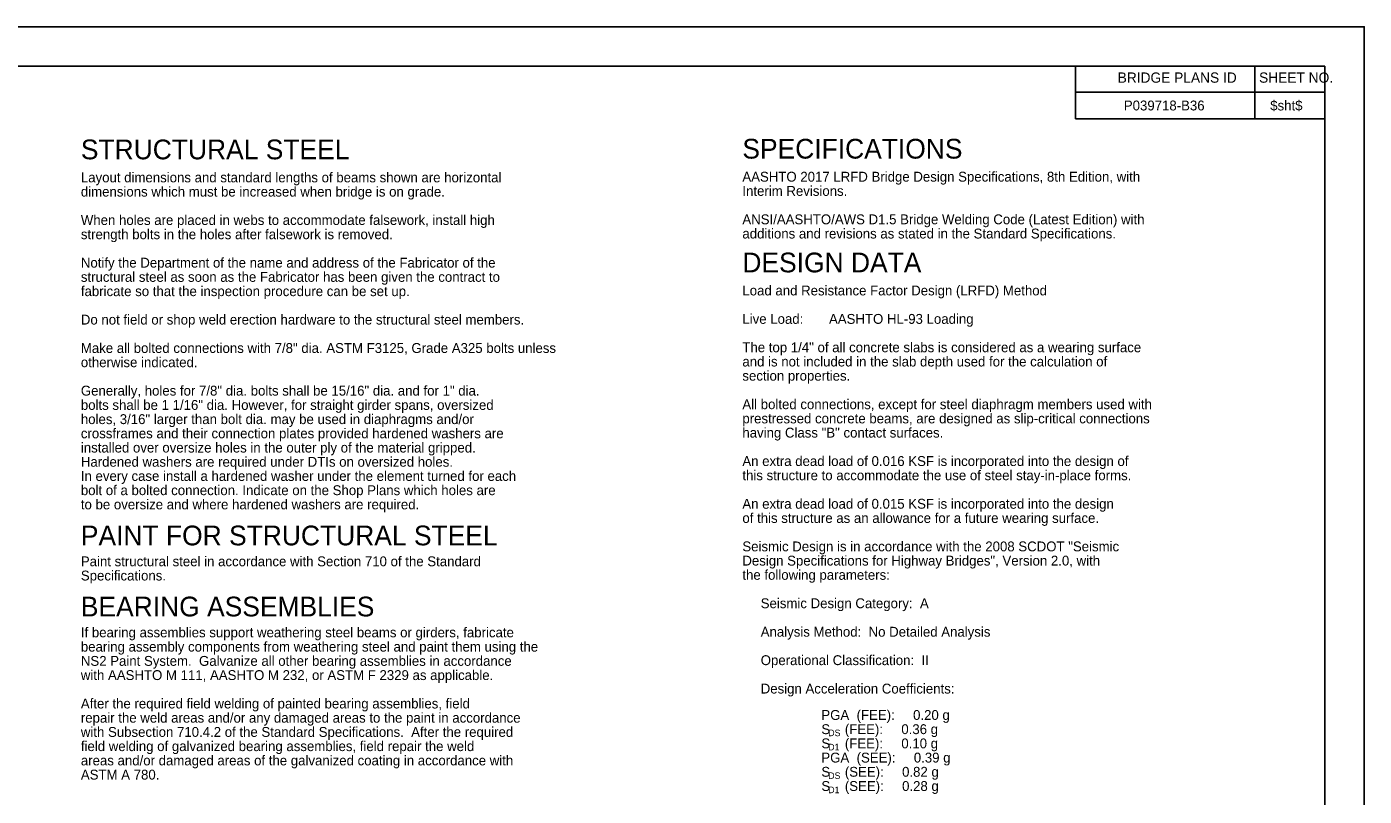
# Model space of a CAD drawing. Extents: x -1.3 to 34.8, y 0.8 to 22.8.
# Drawn here: x 17.75 to 34.68, y 13.07 to 22.82 of the extents above; entities that cross this region are included whole.
import ezdxf

# ---------------------------------------------------------------- set-up
doc = ezdxf.new("R2010")
doc.units = 0
for name, color, linetype in [('BR_BORDER LINES', 7, 'Continuous'), ('BR_TEXT', 7, 'Continuous'), ('Level 31', 7, 'Continuous')]:
    doc.layers.add(name, color=color, linetype=linetype)

msp = doc.modelspace()

# ---------------------------------------------------------------- linework, layer by layer
at = {"layer": 'BR_BORDER LINES'}
for p, q in [((34.177, 22.318), (0.511, 22.318)), ((31.024, 21.651), (31.024, 22.318)), ((33.291, 21.651), (33.291, 22.318)), ((34.177, 1.318), (34.177, 22.318)), ((31.024, 21.989), (34.177, 21.989)), ((33.291, 21.989), (34.177, 21.989)), ((34.177, 21.651), (31.024, 21.651))]:
    msp.add_line(p, q, dxfattribs=at)
at = {"layer": 'Level 31'}
msp.add_lwpolyline([(-1.323, 0.818), (34.677, 0.818), (34.677, 22.818), (-1.323, 22.818)], close=True, dxfattribs=at)

# ---------------------------------------------------------------- texts
at = {"layer": 'BR_TEXT'}
for s, height, p in [('BRIDGE PLANS ID', 0.13, (31.556, 22.109)), ('SHEET NO.', 0.13, (33.346, 22.109)), ('P039718-B36', 0.125, (31.634, 21.758)), ('$sht$', 0.125, (33.487, 21.758)), ('STRUCTURAL STEEL', 0.25, (18.431, 21.139)), ('SPECIFICATIONS', 0.25, (26.805, 21.148)), ('Layout dimensions and standard lengths of beams shown are horizontal ', 0.125, (18.431, 20.847)), ('AASHTO 2017 LRFD Bridge Design Specifications, 8th Edition, with', 0.125, (26.805, 20.856)), ('dimensions which must be increased when bridge is on grade.', 0.125, (18.431, 20.667)), ('Interim Revisions. ', 0.125, (26.805, 20.676)), ('When holes are placed in webs to accommodate falsework, install high', 0.125, (18.431, 20.307)), ('ANSI/AASHTO/AWS D1.5 Bridge Welding Code (Latest Edition) with', 0.125, (26.805, 20.316)), ('strength bolts in the holes after falsework is removed.', 0.125, (18.431, 20.127)), ('additions and revisions as stated in the Standard Specifications.', 0.125, (26.805, 20.136)), ('Notify the Department of the name and address of the Fabricator of the ', 0.125, (18.431, 19.767)), ('DESIGN DATA', 0.25, (26.805, 19.707)), ('structural steel as soon as the Fabricator has been given the contract to ', 0.125, (18.431, 19.587)), ('fabricate so that the inspection procedure can be set up.', 0.125, (18.431, 19.406)), ('Load and Resistance Factor Design (LRFD) Method', 0.125, (26.805, 19.415)), ('Do not field or shop weld erection hardware to the structural steel members. ', 0.125, (18.431, 19.046)), ('Live Load:       AASHTO HL-93 Loading ', 0.125, (26.805, 19.055)), ('Make all bolted connections with 7/8" dia. ASTM F3125, Grade A325 bolts unless', 0.125, (18.431, 18.686)), ('The top 1/4" of all concrete slabs is considered as a wearing surface ', 0.125, (26.805, 18.695)), ('otherwise indicated.', 0.125, (18.431, 18.506)), ('and is not included in the slab depth used for the calculation of ', 0.125, (26.805, 18.515)), ('section properties.', 0.125, (26.805, 18.335)), ('Generally, holes for 7/8" dia. bolts shall be 15/16" dia. and for 1" dia.', 0.125, (18.431, 18.146)), ('bolts shall be 1 1/16" dia. However, for straight girder spans, oversized', 0.125, (18.431, 17.965)), ('All bolted connections, except for steel diaphragm members used with', 0.125, (26.805, 17.974)), ('holes, 3/16" larger than bolt dia. may be used in diaphragms and/or', 0.125, (18.431, 17.785)), ('prestressed concrete beams, are designed as slip-critical connections', 0.125, (26.805, 17.794)), ('crossframes and their connection plates provided hardened washers are', 0.125, (18.431, 17.605)), ('having Class "B" contact surfaces.', 0.125, (26.805, 17.614)), ('installed over oversize holes in the outer ply of the material gripped. ', 0.125, (18.431, 17.425)), ('Hardened washers are required under DTIs on oversized holes.', 0.125, (18.431, 17.245)), ('An extra dead load of 0.016 KSF is incorporated into the design of ', 0.125, (26.805, 17.254)), ('In every case install a hardened washer under the element turned for each', 0.125, (18.431, 17.065)), ('this structure to accommodate the use of steel stay-in-place forms.', 0.125, (26.805, 17.074)), ('bolt of a bolted connection. Indicate on the Shop Plans which holes are', 0.125, (18.431, 16.885)), ('to be oversize and where hardened washers are required. ', 0.125, (18.431, 16.705)), ('An extra dead load of 0.015 KSF is incorporated into the design', 0.125, (26.805, 16.713)), ('of this structure as an allowance for a future wearing surface.', 0.125, (26.805, 16.533)), ('PAINT FOR STRUCTURAL STEEL', 0.25, (18.431, 16.249)), ('Seismic Design is in accordance with the 2008 SCDOT "Seismic', 0.125, (26.805, 16.173)), ('Paint structural steel in accordance with Section 710 of the Standard ', 0.125, (18.431, 15.984)), ('Design Specifications for Highway Bridges", Version 2.0, with', 0.125, (26.805, 15.993)), ('Specifications.', 0.125, (18.431, 15.804)), ('the following parameters:', 0.125, (26.805, 15.813)), ('BEARING ASSEMBLIES', 0.25, (18.431, 15.349)), ('     Seismic Design Category:  A', 0.125, (26.805, 15.453)), ('If bearing assemblies support weathering steel beams or girders, fabricate ', 0.125, (18.431, 15.084)), ('     Analysis Method:  No Detailed Analysis', 0.125, (26.805, 15.092)), ('bearing assembly components from weathering steel and paint them using the ', 0.125, (18.431, 14.903)), ('NS2 Paint System.  Galvanize all other bearing assemblies in accordance ', 0.125, (18.431, 14.723)), ('     Operational Classification:  II', 0.125, (26.805, 14.732)), ('with AASHTO M 111, AASHTO M 232, or ASTM F 2329 as applicable. ', 0.125, (18.431, 14.543)), ('     Design Acceleration Coefficients:', 0.125, (26.805, 14.372)), ('After the required field welding of painted bearing assemblies, field ', 0.125, (18.431, 14.183)), ('repair the weld areas and/or any damaged areas to the paint in accordance ', 0.125, (18.431, 14.003)), ('PGA  (FEE):     0.20 g', 0.125, (27.805, 14.038)), ('with Subsection 710.4.2 of the Standard Specifications.  After the required ', 0.125, (18.431, 13.823)), ('S    (FEE):     0.36 g', 0.125, (27.805, 13.858)), ('DS', 0.0833, (27.892, 13.832)), ('field welding of galvanized bearing assemblies, field repair the weld ', 0.125, (18.431, 13.643)), ('S    (FEE):     0.10 g', 0.125, (27.805, 13.678)), ('D1', 0.0833, (27.892, 13.652)), ('areas and/or damaged areas of the galvanized coating in accordance with ', 0.125, (18.431, 13.462)), ('PGA  (SEE):     0.39 g', 0.125, (27.805, 13.498)), ('ASTM A 780.', 0.125, (18.431, 13.282)), ('S    (SEE):     0.82 g', 0.125, (27.805, 13.318)), ('S    (SEE):     0.28 g', 0.125, (27.805, 13.138)), ('DS', 0.0833, (27.892, 13.29)), ('D1', 0.0833, (27.892, 13.11))]:
    msp.add_text(s, height=height, dxfattribs=at).set_placement(p)

doc.saveas('drawing.dxf')
